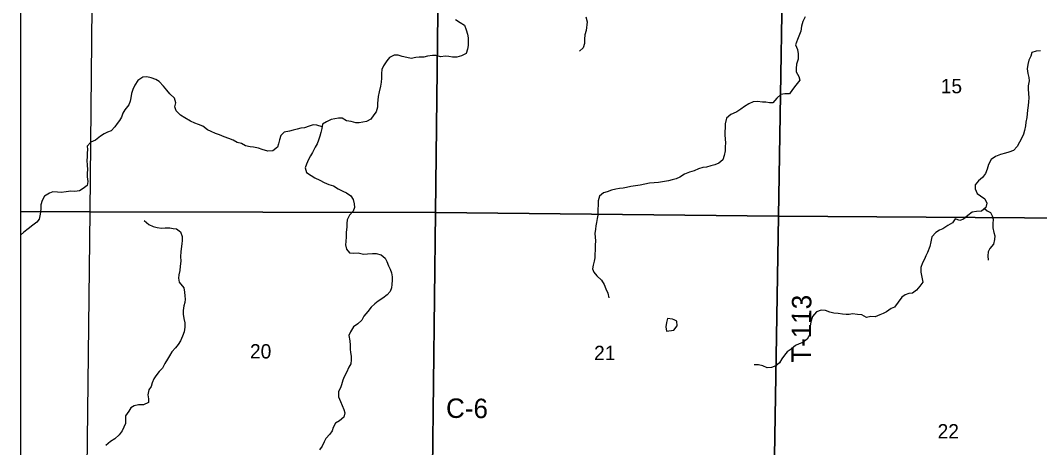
# Model space of a CAD drawing. Extents: x 1772825 to 1773716, y 1138558 to 1139032.
# Drawn here: x 1772825.358 to 1772826.846, y 1138559.287 to 1138559.911 of the extents above; entities that cross this region are included whole.
import ezdxf

# ---------------------------------------------------------------- set-up
doc = ezdxf.new("R2010")
doc.units = 0
for name, color, linetype in [('GM_X_County_Road_Text', 7, 'Continuous'), ('GM_X_Minor_Lake', 7, 'Continuous'), ('GM_X_Minor_River', 7, 'Continuous'), ('GM_X_Section', 7, 'Continuous'), ('GM_X_Section_Text', 7, 'Continuous'), ('GM_X_Township', 7, 'Continuous'), ('GM_X_Township_Road_Text', 7, 'Continuous')]:
    doc.layers.add(name, color=color, linetype=linetype)

msp = doc.modelspace()

# ---------------------------------------------------------------- linework, layer by layer
at = {"layer": 'GM_X_Minor_Lake'}
for points in [[(1772826.3125, 1138559.4731), (1772826.3098, 1138559.4743), (1772826.3028, 1138559.4754), (1772826.3011, 1138559.4692), (1772826.3004, 1138559.4629), (1772826.3013, 1138559.4568)], [(1772826.3013, 1138559.4568), (1772826.3119, 1138559.4583), (1772826.3166, 1138559.4648), (1772826.3161, 1138559.4714), (1772826.3125, 1138559.4731)]]:
    msp.add_lwpolyline(points, dxfattribs=at)
at = {"layer": 'GM_X_Minor_River'}
for points in [[(1772825.9932, 1138559.9121), (1772825.9998, 1138559.9076), (1772826.0061, 1138559.9036), (1772826.0085, 1138559.8968), (1772826.0104, 1138559.8903), (1772826.0114, 1138559.8854), (1772826.0114, 1138559.8797), (1772826.0118, 1138559.8738), (1772826.0108, 1138559.8687), (1772826.0089, 1138559.8621), (1772826.0019, 1138559.8587), (1772825.9953, 1138559.857), (1772825.9885, 1138559.857), (1772825.9836, 1138559.8579), (1772825.9787, 1138559.8585), (1772825.9711, 1138559.8575), (1772825.9649, 1138559.8592), (1772825.9596, 1138559.8594), (1772825.9524, 1138559.8583), (1772825.9471, 1138559.8571), (1772825.9403, 1138559.8567), (1772825.9354, 1138559.8564), (1772825.9285, 1138559.855), (1772825.9219, 1138559.8564), (1772825.9155, 1138559.8581), (1772825.9096, 1138559.8598), (1772825.9034, 1138559.8598), (1772825.897, 1138559.8563), (1772825.8928, 1138559.8516), (1772825.8879, 1138559.8442), (1772825.8858, 1138559.8389), (1772825.8852, 1138559.833), (1772825.8849, 1138559.8262), (1772825.8847, 1138559.8203), (1772825.8835, 1138559.8144), (1772825.8817, 1138559.8061), (1772825.8801, 1138559.7993), (1772825.8794, 1138559.7894), (1772825.8792, 1138559.7839), (1772825.8773, 1138559.7773), (1772825.8737, 1138559.7725), (1772825.8697, 1138559.7665), (1772825.8633, 1138559.7632), (1772825.8576, 1138559.7621), (1772825.8525, 1138559.761), (1772825.8476, 1138559.761), (1772825.8406, 1138559.7629), (1772825.8342, 1138559.764)], [(1772826.1835, 1138559.9156), (1772826.1852, 1138559.9086), (1772826.184, 1138559.8961), (1772826.182, 1138559.8893), (1772826.1816, 1138559.8834), (1772826.1814, 1138559.8767), (1772826.1797, 1138559.8707), (1772826.174, 1138559.8659)], [(1772826.5035, 1138559.9156), (1772826.5004, 1138559.9092), (1772826.4982, 1138559.902), (1772826.4971, 1138559.895), (1772826.4953, 1138559.89), (1772826.4924, 1138559.8829), (1772826.4897, 1138559.8751), (1772826.4925, 1138559.8679), (1772826.4936, 1138559.862), (1772826.4932, 1138559.854), (1772826.4908, 1138559.8466), (1772826.4906, 1138559.8404), (1772826.4906, 1138559.8356), (1772826.4941, 1138559.8286), (1772826.4956, 1138559.8231), (1772826.4898, 1138559.8161), (1772826.4852, 1138559.8099), (1772826.4805, 1138559.8036), (1772826.4738, 1138559.8033), (1772826.4681, 1138559.8026), (1772826.462, 1138559.797), (1772826.4564, 1138559.7902), (1772826.4513, 1138559.7902), (1772826.446, 1138559.791), (1772826.4411, 1138559.7914), (1772826.4339, 1138559.7922), (1772826.4278, 1138559.7915), (1772826.4215, 1138559.7889), (1772826.415, 1138559.7848), (1772826.4099, 1138559.781), (1772826.404, 1138559.7773), (1772826.3984, 1138559.7746)], [(1772826.8471, 1138559.8662), (1772826.841, 1138559.8656), (1772826.8347, 1138559.8638), (1772826.8328, 1138559.8583), (1772826.8301, 1138559.8524), (1772826.8285, 1138559.8464), (1772826.8279, 1138559.8397), (1772826.8286, 1138559.8331), (1772826.8303, 1138559.827), (1772826.8304, 1138559.8223), (1772826.8289, 1138559.8153), (1772826.829, 1138559.81), (1772826.8299, 1138559.7976), (1772826.8295, 1138559.7915), (1772826.8292, 1138559.7862), (1772826.8282, 1138559.7796), (1772826.8276, 1138559.7741), (1772826.827, 1138559.769), (1772826.8258, 1138559.762), (1772826.825, 1138559.7567), (1772826.8239, 1138559.75), (1772826.8221, 1138559.7444), (1772826.82, 1138559.7393), (1772826.8165, 1138559.7326), (1772826.8129, 1138559.7264), (1772826.8075, 1138559.7208), (1772826.8007, 1138559.7181), (1772826.7959, 1138559.7169), (1772826.7887, 1138559.715), (1772826.7816, 1138559.7118), (1772826.7753, 1138559.7073), (1772826.7713, 1138559.7002), (1772826.7692, 1138559.6935), (1772826.7669, 1138559.6869), (1772826.7624, 1138559.6811), (1772826.7567, 1138559.6762), (1772826.7516, 1138559.6703), (1772826.7519, 1138559.6646), (1772826.7545, 1138559.6578), (1772826.7594, 1138559.6545), (1772826.7658, 1138559.6501), (1772826.7688, 1138559.6436), (1772826.7674, 1138559.6376), (1772826.761, 1138559.6319), (1772826.7537, 1138559.6314), (1772826.7473, 1138559.6307), (1772826.741, 1138559.6258), (1772826.7349, 1138559.6204), (1772826.7294, 1138559.6185), (1772826.7225, 1138559.621)], [(1772825.7983, 1138559.7551), (1772825.7905, 1138559.7575), (1772825.7854, 1138559.7579), (1772825.7795, 1138559.7562), (1772825.7725, 1138559.7539), (1772825.7673, 1138559.753), (1772825.7618, 1138559.7516), (1772825.7559, 1138559.7503), (1772825.7508, 1138559.7488), (1772825.7432, 1138559.7473), (1772825.7379, 1138559.7423), (1772825.736, 1138559.7363), (1772825.7347, 1138559.7304), (1772825.7332, 1138559.7253), (1772825.7266, 1138559.7203), (1772825.719, 1138559.7198), (1772825.7111, 1138559.7221), (1772825.7054, 1138559.7238), (1772825.6984, 1138559.7253), (1772825.6935, 1138559.7258), (1772825.6867, 1138559.7273), (1772825.6805, 1138559.731), (1772825.6744, 1138559.7323), (1772825.6685, 1138559.7357), (1772825.6623, 1138559.738), (1772825.6555, 1138559.7404), (1772825.6485, 1138559.7436), (1772825.6428, 1138559.7453), (1772825.6364, 1138559.7482), (1772825.6311, 1138559.751), (1772825.6243, 1138559.756), (1772825.618, 1138559.7584), (1772825.6127, 1138559.7605), (1772825.6061, 1138559.7637), (1772825.5978, 1138559.7685), (1772825.5916, 1138559.7724), (1772825.5851, 1138559.7785), (1772825.5834, 1138559.7844), (1772825.5849, 1138559.7904), (1772825.5829, 1138559.7969), (1772825.5759, 1138559.8035), (1772825.5719, 1138559.8088), (1772825.567, 1138559.8145), (1772825.5607, 1138559.8212), (1772825.5558, 1138559.8244), (1772825.549, 1138559.8266), (1772825.5426, 1138559.8283), (1772825.5369, 1138559.8276), (1772825.5293, 1138559.8227), (1772825.5248, 1138559.816), (1772825.5222, 1138559.8096), (1772825.5203, 1138559.8037), (1772825.5193, 1138559.7974), (1772825.5182, 1138559.7925), (1772825.5161, 1138559.7872), (1772825.5103, 1138559.78), (1772825.5074, 1138559.7753), (1772825.5057, 1138559.7694), (1772825.5025, 1138559.7646), (1772825.4991, 1138559.7599), (1772825.4959, 1138559.7552), (1772825.4904, 1138559.7495), (1772825.4851, 1138559.7474), (1772825.4802, 1138559.7451), (1772825.4751, 1138559.7417), (1772825.4675, 1138559.7356), (1772825.4609, 1138559.733), (1772825.4556, 1138559.7269), (1772825.456, 1138559.7221), (1772825.4556, 1138559.7166), (1772825.4552, 1138559.7115), (1772825.4549, 1138559.706), (1772825.4552, 1138559.6994), (1772825.4558, 1138559.6928), (1772825.4556, 1138559.6876), (1772825.4554, 1138559.6821), (1772825.4566, 1138559.6755), (1772825.4556, 1138559.6694), (1772825.4496, 1138559.6649), (1772825.4441, 1138559.6617), (1772825.4373, 1138559.6607), (1772825.4314, 1138559.6611), (1772825.4246, 1138559.6603), (1772825.4176, 1138559.6592), (1772825.4121, 1138559.6599), (1772825.4055, 1138559.6603), (1772825.4006, 1138559.6584), (1772825.3932, 1138559.6539), (1772825.3896, 1138559.6478), (1772825.3877, 1138559.6415), (1772825.3877, 1138559.6357), (1772825.3873, 1138559.6305), (1772825.3862, 1138559.6254), (1772825.3851, 1138559.6205), (1772825.3817, 1138559.6158), (1772825.376, 1138559.6116), (1772825.3692, 1138559.6063), (1772825.3628, 1138559.6015), (1772825.3579, 1138559.5968)], [(1772826.3984, 1138559.7746), (1772826.3949, 1138559.7731), (1772826.3885, 1138559.7676), (1772826.387, 1138559.7598), (1772826.3868, 1138559.7538), (1772826.3862, 1138559.7486), (1772826.3864, 1138559.7437), (1772826.387, 1138559.7373), (1772826.3873, 1138559.7318), (1772826.387, 1138559.7259), (1772826.387, 1138559.72), (1772826.3853, 1138559.7132), (1772826.3834, 1138559.7069), (1772826.3777, 1138559.702), (1772826.3715, 1138559.6997), (1772826.366, 1138559.698), (1772826.3594, 1138559.6965), (1772826.3544, 1138559.6957), (1772826.348, 1138559.694), (1772826.3414, 1138559.6908), (1772826.3346, 1138559.6891), (1772826.3274, 1138559.6863), (1772826.3204, 1138559.6815), (1772826.3151, 1138559.6792), (1772826.3096, 1138559.6779), (1772826.3039, 1138559.6764), (1772826.2951, 1138559.6747), (1772826.2896, 1138559.6741), (1772826.2833, 1138559.6732), (1772826.2765, 1138559.6728), (1772826.2693, 1138559.6713), (1772826.2629, 1138559.6701), (1772826.2557, 1138559.6688), (1772826.2491, 1138559.668), (1772826.2429, 1138559.6667), (1772826.2378, 1138559.6657), (1772826.2323, 1138559.665), (1772826.227, 1138559.664), (1772826.2211, 1138559.6627), (1772826.2147, 1138559.6602), (1772826.2092, 1138559.6589), (1772826.2032, 1138559.654), (1772826.2016, 1138559.647), (1772826.2016, 1138559.6415), (1772826.2011, 1138559.6346), (1772826.2007, 1138559.6263), (1772826.1998, 1138559.6214), (1772826.1988, 1138559.6157), (1772826.1982, 1138559.6107), (1772826.1975, 1138559.6056), (1772826.1967, 1138559.5996), (1772826.1969, 1138559.5939), (1772826.1973, 1138559.5889), (1772826.1971, 1138559.5825), (1772826.1969, 1138559.5753), (1772826.1966, 1138559.5694), (1772826.1964, 1138559.5639), (1772826.1954, 1138559.559), (1772826.1941, 1138559.5533), (1772826.1931, 1138559.5476), (1772826.195, 1138559.5427), (1772826.1994, 1138559.5376), (1772826.2064, 1138559.5315), (1772826.21, 1138559.5247), (1772826.2126, 1138559.5188), (1772826.2153, 1138559.5122), (1772826.217, 1138559.5053)], [(1772825.8342, 1138559.764), (1772825.8276, 1138559.7678), (1772825.8221, 1138559.7676), (1772825.8168, 1138559.767), (1772825.8117, 1138559.7661), (1772825.8047, 1138559.7623), (1772825.799, 1138559.7589), (1772825.7979, 1138559.7528), (1772825.7966, 1138559.7469), (1772825.7949, 1138559.7416), (1772825.7932, 1138559.7355), (1772825.7913, 1138559.7304), (1772825.7884, 1138559.7253), (1772825.7845, 1138559.7179), (1772825.7812, 1138559.713), (1772825.7784, 1138559.7073), (1772825.7756, 1138559.7007), (1772825.7737, 1138559.6953), (1772825.7756, 1138559.6887), (1772825.7826, 1138559.684), (1772825.7879, 1138559.6809), (1772825.7949, 1138559.6773), (1772825.8013, 1138559.6741), (1772825.8081, 1138559.6709), (1772825.8149, 1138559.6688), (1772825.8217, 1138559.6648), (1772825.8285, 1138559.661), (1772825.834, 1138559.6586), (1772825.8403, 1138559.6544), (1772825.8437, 1138559.6489), (1772825.8452, 1138559.6428), (1772825.8456, 1138559.6372), (1772825.8439, 1138559.6322), (1772825.8386, 1138559.626), (1772825.835, 1138559.6195), (1772825.8344, 1138559.6138), (1772825.8344, 1138559.6085), (1772825.8336, 1138559.6013), (1772825.8335, 1138559.5947), (1772825.8331, 1138559.5877), (1772825.8327, 1138559.5827), (1772825.834, 1138559.5765), (1772825.8382, 1138559.5712), (1772825.8446, 1138559.5706), (1772825.8512, 1138559.5714), (1772825.8586, 1138559.5693), (1772825.8647, 1138559.5695), (1772825.872, 1138559.5701), (1772825.8773, 1138559.5701), (1772825.8845, 1138559.5682), (1772825.8904, 1138559.5634), (1772825.8928, 1138559.5583), (1772825.8953, 1138559.5521), (1772825.8976, 1138559.5471), (1772825.8995, 1138559.5418), (1772825.9008, 1138559.5361), (1772825.9008, 1138559.5314), (1772825.9002, 1138559.5249), (1772825.8997, 1138559.52), (1772825.8978, 1138559.5149), (1772825.8936, 1138559.51), (1772825.8868, 1138559.5048), (1772825.8804, 1138559.5005), (1772825.8755, 1138559.4965), (1772825.8698, 1138559.4917), (1772825.8651, 1138559.4853), (1772825.8592, 1138559.4787), (1772825.8564, 1138559.473), (1772825.8507, 1138559.4673), (1772825.8444, 1138559.4633), (1772825.8397, 1138559.4559), (1772825.8374, 1138559.4506), (1772825.8388, 1138559.4426), (1772825.8392, 1138559.4364), (1772825.8393, 1138559.4303), (1772825.8397, 1138559.4254), (1772825.8407, 1138559.4203), (1772825.841, 1138559.4151), (1772825.8401, 1138559.4091), (1772825.8375, 1138559.404), (1772825.8339, 1138559.3964), (1772825.8306, 1138559.3901), (1772825.8286, 1138559.385), (1772825.8267, 1138559.3785), (1772825.8252, 1138559.3738), (1772825.8225, 1138559.3687), (1772825.8221, 1138559.3609), (1772825.825, 1138559.3541), (1772825.8278, 1138559.348), (1772825.8301, 1138559.3425), (1772825.8318, 1138559.3374), (1772825.8301, 1138559.3311), (1772825.8237, 1138559.3258), (1772825.818, 1138559.3224), (1772825.8146, 1138559.316), (1772825.8129, 1138559.3112), (1772825.8095, 1138559.3065), (1772825.8038, 1138559.3002), (1772825.8012, 1138559.2951), (1772825.7983, 1138559.289), (1772825.7944, 1138559.2835)], [(1772826.7653, 1138559.6357), (1772826.7691, 1138559.6324), (1772826.774, 1138559.6303), (1772826.7767, 1138559.6254), (1772826.7778, 1138559.6204), (1772826.7775, 1138559.6136), (1772826.7775, 1138559.6075), (1772826.7788, 1138559.6011), (1772826.7804, 1138559.5959), (1772826.78, 1138559.5908), (1772826.7784, 1138559.5836), (1772826.7731, 1138559.5774), (1772826.7706, 1138559.5725), (1772826.7703, 1138559.567), (1772826.7705, 1138559.5605)], [(1772826.7225, 1138559.621), (1772826.7187, 1138559.6148), (1772826.7117, 1138559.6109), (1772826.7046, 1138559.6062), (1772826.6995, 1138559.6041), (1772826.6943, 1138559.6009), (1772826.6884, 1138559.5943), (1772826.687, 1138559.5871), (1772826.6856, 1138559.5803), (1772826.682, 1138559.5718), (1772826.6797, 1138559.5669), (1772826.6777, 1138559.5618), (1772826.675, 1138559.5565), (1772826.6723, 1138559.5499), (1772826.6723, 1138559.5427), (1772826.6739, 1138559.5356), (1772826.6756, 1138559.5284), (1772826.6712, 1138559.5224), (1772826.666, 1138559.5167), (1772826.6601, 1138559.5124), (1772826.6548, 1138559.5119), (1772826.6496, 1138559.51), (1772826.6447, 1138559.5066), (1772826.6395, 1138559.4989), (1772826.634, 1138559.4919), (1772826.6292, 1138559.49), (1772826.6223, 1138559.4848), (1772826.6176, 1138559.4827), (1772826.6124, 1138559.4805), (1772826.606, 1138559.4777), (1772826.5993, 1138559.4781), (1772826.5932, 1138559.4767), (1772826.5864, 1138559.4805), (1772826.5798, 1138559.4809), (1772826.5728, 1138559.4823), (1772826.568, 1138559.481), (1772826.5633, 1138559.4809), (1772826.558, 1138559.4817), (1772826.5517, 1138559.4827), (1772826.5455, 1138559.4829), (1772826.5394, 1138559.4845), (1772826.5334, 1138559.4872), (1772826.5269, 1138559.4876), (1772826.5203, 1138559.4848), (1772826.5145, 1138559.4784), (1772826.5118, 1138559.4702), (1772826.5108, 1138559.4642), (1772826.5106, 1138559.4587), (1772826.5102, 1138559.452), (1772826.5063, 1138559.445), (1772826.5004, 1138559.4402), (1772826.4949, 1138559.4381), (1772826.4895, 1138559.4357), (1772826.4832, 1138559.4304), (1772826.4773, 1138559.4267), (1772826.4735, 1138559.4216), (1772826.4693, 1138559.4165), (1772826.466, 1138559.4104), (1772826.4607, 1138559.4063), (1772826.4542, 1138559.4037), (1772826.4481, 1138559.4032), (1772826.4417, 1138559.4063), (1772826.4355, 1138559.4074), (1772826.429, 1138559.4077)], [(1772825.5388, 1138559.6183), (1772825.5453, 1138559.6126), (1772825.5517, 1138559.6094), (1772825.5577, 1138559.608), (1772825.564, 1138559.6073), (1772825.5691, 1138559.6075), (1772825.5759, 1138559.6075), (1772825.5808, 1138559.6069), (1772825.5857, 1138559.606), (1772825.5918, 1138559.6018), (1772825.5942, 1138559.5948), (1772825.594, 1138559.5891), (1772825.5935, 1138559.5844), (1772825.5927, 1138559.5772), (1772825.5922, 1138559.5724), (1772825.5916, 1138559.5656), (1772825.592, 1138559.5588), (1772825.5912, 1138559.5518), (1772825.5905, 1138559.5453), (1772825.5893, 1138559.5392), (1772825.5888, 1138559.5341), (1772825.5899, 1138559.5281), (1772825.5963, 1138559.5203), (1772825.5975, 1138559.5135), (1772825.5982, 1138559.5083), (1772825.5986, 1138559.5034), (1772825.598, 1138559.4985), (1772825.5967, 1138559.4937), (1772825.5956, 1138559.4869), (1772825.5956, 1138559.4816), (1772825.5965, 1138559.4753), (1772825.5978, 1138559.4689), (1772825.5982, 1138559.4625), (1772825.5971, 1138559.4556), (1772825.5944, 1138559.4496), (1772825.5918, 1138559.4427), (1772825.5882, 1138559.4372), (1772825.5842, 1138559.4325), (1772825.5791, 1138559.4264), (1772825.5754, 1138559.4207), (1772825.5729, 1138559.416), (1772825.5689, 1138559.4095), (1772825.5653, 1138559.4027), (1772825.5606, 1138559.3978), (1772825.5555, 1138559.3917), (1772825.5529, 1138559.387), (1772825.5504, 1138559.3813), (1772825.5487, 1138559.3762), (1772825.5455, 1138559.3712), (1772825.544, 1138559.364), (1772825.5447, 1138559.358), (1772825.5449, 1138559.3525), (1772825.5377, 1138559.3494), (1772825.5305, 1138559.3494), (1772825.5241, 1138559.3477), (1772825.5192, 1138559.3447), (1772825.5164, 1138559.3399), (1772825.5116, 1138559.3329), (1772825.5114, 1138559.3272), (1772825.5116, 1138559.3219), (1772825.5088, 1138559.3168), (1772825.5065, 1138559.3113), (1772825.5022, 1138559.3056), (1772825.4959, 1138559.2997), (1772825.4893, 1138559.2958), (1772825.4827, 1138559.2899)]]:
    msp.add_lwpolyline(points, dxfattribs=at)
at = {"layer": 'GM_X_Section'}
for p, q in [((1772825.3579, 1138560.1323), (1772825.3579, 1138559.6317)), ((1772825.3579, 1138559.6317), (1772825.3579, 1138559.1321))]:
    msp.add_line(p, q, dxfattribs=at)
for points in [[(1772825.3579, 1138559.6317), (1772825.4596, 1138559.6311), (1772825.4647, 1138560.1309), (1772825.3579, 1138560.1323)], [(1772825.3579, 1138559.1321), (1772825.4538, 1138559.1316), (1772825.4596, 1138559.6311), (1772825.3579, 1138559.6317)]]:
    msp.add_lwpolyline(points, dxfattribs=at)
for points in [[(1772825.4647, 1138560.1309), (1772825.9696, 1138560.1298), (1772825.964, 1138559.63), (1772825.4596, 1138559.6311)], [(1772825.9696, 1138560.1298), (1772826.4728, 1138560.1264), (1772826.4648, 1138559.6249), (1772825.964, 1138559.63)], [(1772826.9648, 1138560.1213), (1772826.9674, 1138559.6213), (1772826.4648, 1138559.6249), (1772826.4728, 1138560.1264)], [(1772825.4596, 1138559.6311), (1772825.964, 1138559.63), (1772825.9581, 1138559.1314), (1772825.4538, 1138559.1316)], [(1772825.964, 1138559.63), (1772826.4648, 1138559.6249), (1772826.4565, 1138559.1279), (1772825.9581, 1138559.1314)], [(1772826.4648, 1138559.6249), (1772826.9674, 1138559.6213), (1772826.9648, 1138559.1255), (1772826.4565, 1138559.1279)]]:
    msp.add_lwpolyline(points, close=True, dxfattribs=at)
at = {"layer": 'GM_X_Township'}
msp.add_line((1772825.3579, 1138561.138), (1772825.3579, 1138558.1321), dxfattribs=at)

# ---------------------------------------------------------------- texts
at = {"layer": 'GM_X_County_Road_Text'}
msp.add_text('C-6', height=0.02841, rotation=359.5396, dxfattribs=at).set_placement((1772825.9792, 1138559.3302))
at = {"layer": 'GM_X_Section_Text'}
for s, p in [('15', (1772826.7015, 1138559.8042)), ('20', (1772825.6931, 1138559.4169)), ('21', (1772826.1954, 1138559.4145)), ('22', (1772826.6969, 1138559.3001))]:
    msp.add_text(s, height=0.02093, rotation=0, dxfattribs=at).set_placement(p)
at = {"layer": 'GM_X_Township_Road_Text'}
msp.add_text('T-113', height=0.02841, rotation=89.4429, dxfattribs=at).set_placement((1772826.5118, 1138559.4105))

doc.saveas('drawing.dxf')
